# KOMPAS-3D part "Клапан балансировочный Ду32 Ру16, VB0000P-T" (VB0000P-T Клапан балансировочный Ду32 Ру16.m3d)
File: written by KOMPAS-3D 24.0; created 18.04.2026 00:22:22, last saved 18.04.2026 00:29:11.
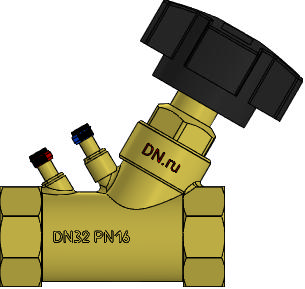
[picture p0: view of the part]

Document properties: Автор: tyuri; Полное имя файла: E:\Работа\Зайцев\АУТСОРС\Диман\Балансировка\VB0000P-T Клапан балансировочный DN.ru Ду15-50 Ру16\DN32\VB0000P-T Клапан балансировочный Ду32 Ру16.m3d

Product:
- Body: Тело 2  | qty 1
    Масса: 1.39321
- Part/product: Клапан балансировочный Ду32 Ру16  | designation VB0000P-T
    Масса: 0.73
    Раздел спецификации: Прочие изделия
    Примечание: D080-01094

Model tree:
1. Операция без истории:1

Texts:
  VB0000P-T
